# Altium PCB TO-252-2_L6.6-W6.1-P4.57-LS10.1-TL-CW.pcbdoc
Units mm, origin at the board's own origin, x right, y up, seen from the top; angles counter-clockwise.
Board outline 24.15 x 19.39 mm, 2 copper layers (Top Layer, Bottom Layer), stack 0 mm thick; 1 components, 0 nets, 3 pads, 0 vias.
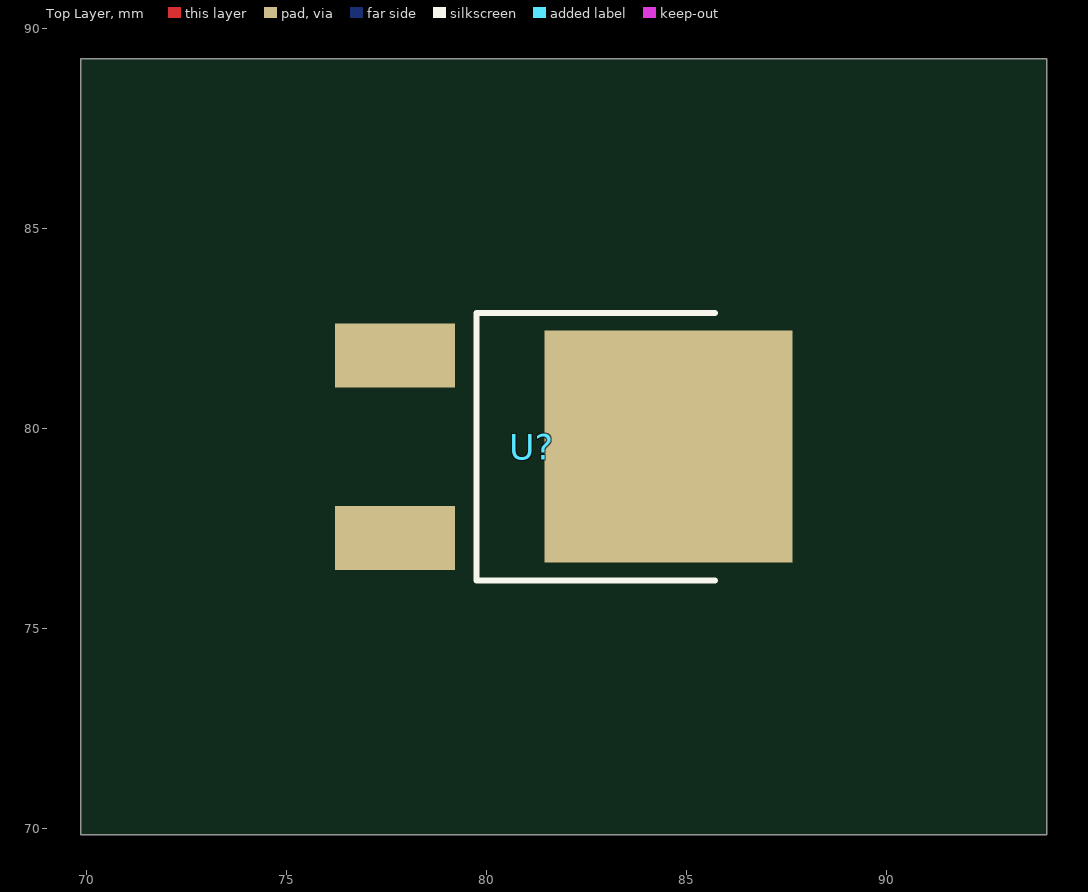
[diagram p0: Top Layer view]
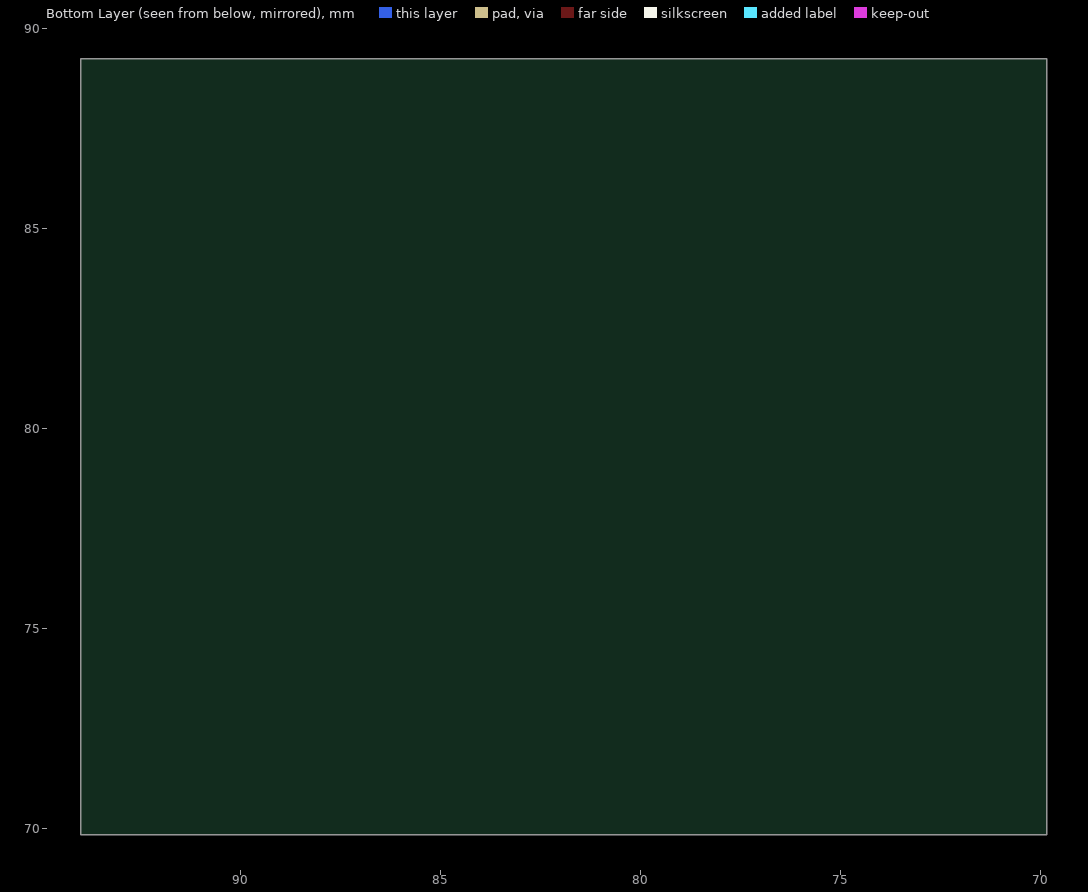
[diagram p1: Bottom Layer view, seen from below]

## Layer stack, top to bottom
Top Layer: signal copper (thickness not stored)
Bottom Layer: signal copper (thickness not stored)

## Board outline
93.998,69.85 69.85,69.85 69.85,89.242 93.998,89.242

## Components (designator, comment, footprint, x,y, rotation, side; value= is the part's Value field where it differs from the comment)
U? "" TO-252-2_L6.6-W6.1-P4.57-LS10.1-TL-CW 81.124,79.546 r0 top

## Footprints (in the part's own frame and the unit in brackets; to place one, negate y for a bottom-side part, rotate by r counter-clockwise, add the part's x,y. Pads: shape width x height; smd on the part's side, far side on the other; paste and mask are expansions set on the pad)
TO-252-2_L6.6-W6.1-P4.57-LS10.1-TL-CW [mm]
  rect 3x1.6 smd: 1(-3.424,2.285) 3(-3.424,-2.285)
  rect 6.2x5.8 smd: 2(3.424,0)
  silkscreen extent -1.38,-3.35 4.58,3.35

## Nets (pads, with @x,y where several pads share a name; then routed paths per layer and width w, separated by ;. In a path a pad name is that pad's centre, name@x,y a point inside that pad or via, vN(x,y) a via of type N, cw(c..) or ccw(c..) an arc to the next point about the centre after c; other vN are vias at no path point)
pads on no net: U?.1 U?.2 U?.3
